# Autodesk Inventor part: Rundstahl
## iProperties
Created: 2007-11
Part Number: Rundstahl
Document SubType Name: Modeling
Designer: Benno
Manufacturer: Standard
Standards Organization: Custom
Author: Benno
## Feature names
1. Extrusion1
2. Extrusion2
3. Bohrung1 [Hole]
4. Extrusion3
5. Extrusion4
6. Extrusion5
7. Extrusion6
8. Fase1 [Chamfer]
